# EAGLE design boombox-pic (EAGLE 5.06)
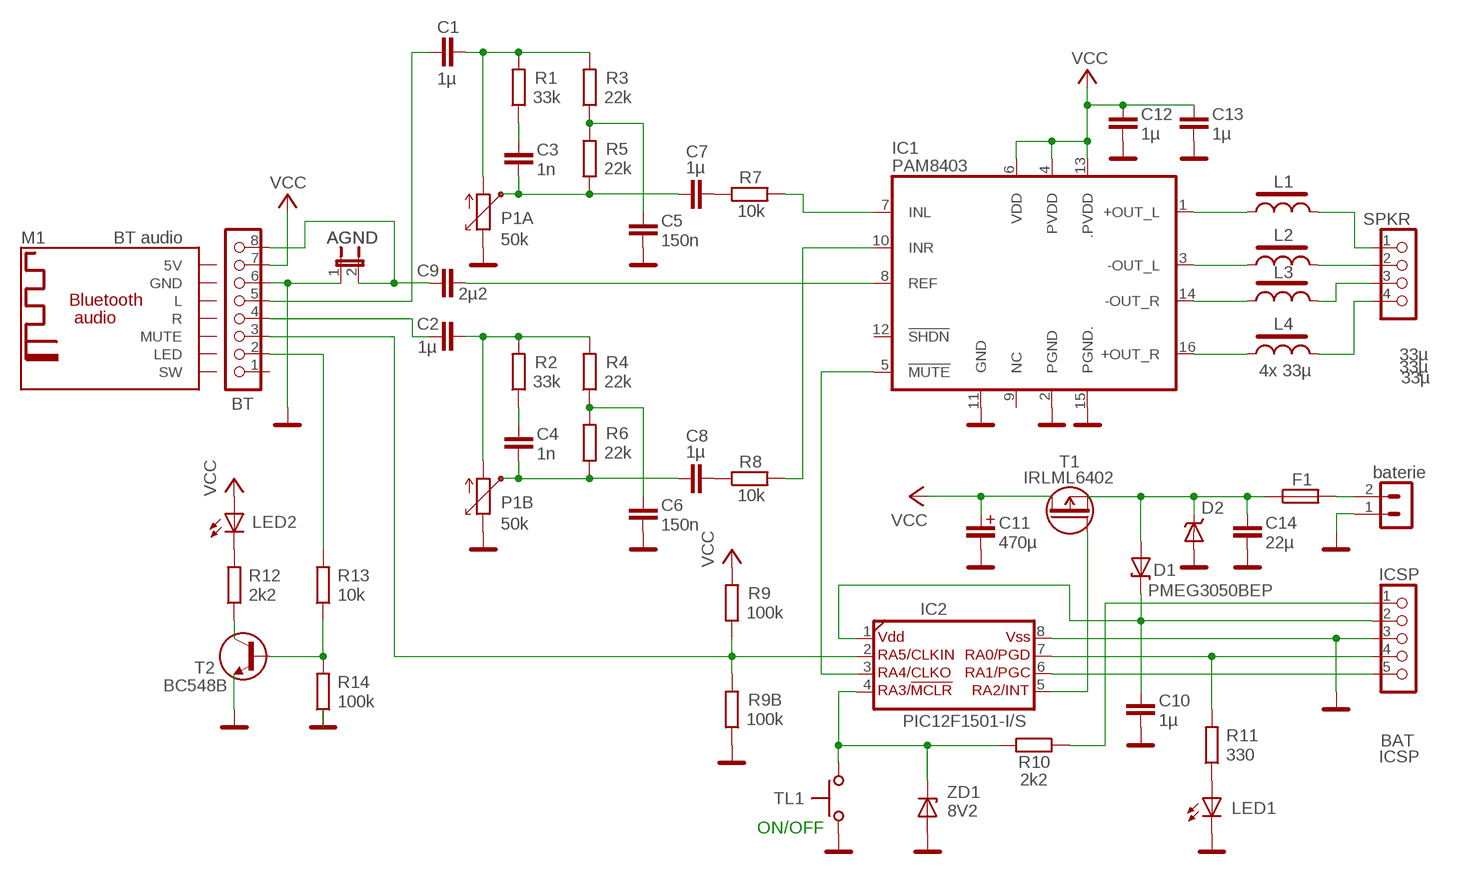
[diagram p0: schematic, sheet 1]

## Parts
AGND  JP2E_V  [1X02]
BAT  baterie  KONZ-02JST-XH  [JST-XH2]
BT  PINHD-1X8  [1X08]
C1  1µ  CSMD0805_KEMET_REFLOW  [C0805K]
C2  1µ  CSMD0805_KEMET_REFLOW  [C0805K]
C3  1n  C_KER_RM5  [C_KER_RM5]
C4  1n  C_KER_RM5  [C_KER_RM5]
C5  150n  C_5-7X3  [C5-7X3]
C6  150n  C_5-7X3  [C5-7X3]
C7  1µ  CSMD0805_KEMET_REFLOW  [C0805K]
C8  1µ  CSMD0805_KEMET_REFLOW  [C0805K]
C9  2µ2  CSMD0805_KEMET_REFLOW  [C0805K]
C10  1µ  CSMD0805_KEMET_REFLOW  [C0805K]
C11  470µ  C_ELYT_3.5-8  [CEL_3.5-8]
C12  1µ  CSMD0805_KEMET_REFLOW  [C0805K]
C13  1µ  CSMD0805_KEMET_REFLOW  [C0805K]
C14  22µ  CSMD1210  [C1210K]
D1  PMEG3050BEP  DIODA-SCHOTTKYSMA-DO214AC  [SMA-DO214AC]
D2  TRANSIL_SMA  [SMA-DO214AC]
F1  POJISTKA_MST-MSF  [POJISTKA_MST_MSF]
IC1  PAM8403  [SO16-RN]
IC2  PIC12F1501-I/S  [SO08-RN]
ICSP  ICSP  PINHD-1X5  [1X05]
L1  33µ  TLUMIVKA_SMD_SMT54  [TLUMIVKA_SMD_SMT54]
L2  33µ  TLUMIVKA_SMD_SMT54  [TLUMIVKA_SMD_SMT54]
L3  33µ  TLUMIVKA_SMD_SMT54  [TLUMIVKA_SMD_SMT54]
L4  4x 33µ  TLUMIVKA_SMD_SMT54  [TLUMIVKA_SMD_SMT54]
LED1  LEDSQR2X5  [LED2X5]
LED2  LEDSQR2X5  [LED2X5]
M1  BT audio  MODUL_BLUETOOTH  [MODUL_BLUETOOTH]
P1  50k  POT_STEREORK097  [RK097-DUAL-ELEMENT]
R1  33k  REZISTOR_SMD0805_KEMET_REFLOW  [C0805K]
R2  33k  REZISTOR_SMD0805_KEMET_REFLOW  [C0805K]
R3  22k  REZISTOR_SMD0805_KEMET_REFLOW  [C0805K]
R4  22k  REZISTOR_SMD0805_KEMET_REFLOW  [C0805K]
R5  22k  REZISTOR_SMD0805_KEMET_REFLOW  [C0805K]
R6  22k  REZISTOR_SMD0805_KEMET_REFLOW  [C0805K]
R7  10k  REZISTOR_SMD0805_KEMET_REFLOW  [C0805K]
R8  10k  REZISTOR_SMD0805_KEMET_REFLOW  [C0805K]
R9  100k  REZISTOR_SMD0805_KEMET_REFLOW  [C0805K]
R9B  100k  REZISTOR_SMD0805_KEMET_REFLOW  [C0805K]
R10  2k2  REZISTOR_SMD0805_KEMET_REFLOW  [C0805K]
R11  330  REZISTOR_SMD0805_KEMET_REFLOW  [C0805K]
R12  2k2  REZISTOR_SMD0805_KEMET_REFLOW  [C0805K]
R13  10k  REZISTOR_SMD0805_KEMET_REFLOW  [C0805K]
R14  100k  REZISTOR_SMD0805_KEMET_REFLOW  [C0805K]
SPKR  PINHD-1X4  [1X04]
T1  IRLML6402  T_PFETSOT23  [SOT23-R]
T2  BC548B  T_NPNSOT23  [SOT23-R]
TL1  TLACITKO-2P_2PIN  [2PIN_2.5MM]
ZD1  8V2  DIODA_ZENER_SOT23  [SOT23-R]

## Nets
AGND: AGND.2 BT.8 C9.1
GND: AGND.1 BAT.1 BT.6 C5.2 C6.2 C10.2 C11.- C12.2 C13.2 C14.2 D2.A IC1.2(PGND) IC1.11(GND) IC1.15(PGND.) IC2.8(VSS) ICSP.3 LED1.K(C) P1.3 P1.6 R9B.1 R14.1 T2.E TL1.P$1(P) ZD1.B(A)
N$1: BT.5 C1.1
N$2: BT.4 C2.1
N$3: C4.1 R2.1
N$4: C3.1 R1.1
N$5: C5.1 R3.1 R5.2
N$6: C6.1 R4.1 R6.2
N$7: C2.2 P1.4 R2.2 R4.2
N$8: C4.2 C8.1 P1.5 R6.1
N$9: C1.2 P1.1 R1.2 R3.2
N$10: C3.2 C7.1 P1.2 R5.1
N$11: C7.2 R7.1
N$12: C8.2 R8.1
N$13: IC1.10(INR) R8.2
N$14: IC1.7(INL) R7.2
N$15: C9.2 IC1.8(REF)
N$16: IC1.1(+OUT_L) L1.F1
N$17: IC1.3(-OUT_L) L2.F1
N$18: IC1.14(-OUT_R) L3.F1
N$19: IC1.16(+OUT_R) L4.F1
N$20: L1.F2 SPKR.1
N$21: L2.F2 SPKR.2
N$22: L3.F2 SPKR.3
N$23: L4.F2 SPKR.4
N$24: BAT.2 F1.F2
N$25: IC2.7(RA0/AN0) ICSP.4 R11.2
N$26: IC2.6(RA1/AN1) ICSP.5
N$27: C10.1 D1.K IC2.1(VCC) ICSP.2
N$28: BT.3 IC2.2(RA5/CLKIN) R9.1 R9B.2
N$29: IC1.5(!MUTE) IC2.3(RA4/AN3)
N$30: ICSP.1 R10.2
N$31: IC2.4(RA3/!MCLR) R10.1 TL1.P$2(S) ZD1.C(K)
N$32: LED1.A R11.1
N$33: C14.1 D1.A D2.K F1.F1 T1.E(S)
N$34: IC2.5(RA2/AN2) T1.B(G)
N$37: LED2.K(C) R12.2
N$38: BT.2 R13.2
N$39: R13.1 R14.2 T2.B
N$40: R12.1 T2.C
VCC: BT.7 C11.+ C12.1 C13.1 IC1.4(PVDD) IC1.6(VDD) IC1.13(.PVDD) LED2.A R9.2 T1.C(D)
Unconnected: BT.1 IC1.9(NC) IC1.12(!SHDN) M1.L M1.LED M1.MUTE M1.R M1.SW

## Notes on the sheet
- ON/OFF

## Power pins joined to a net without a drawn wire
5V: M1.5V
GND: M1.GND

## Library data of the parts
AGND = #bcs_pinhead:JP2E: JUMPER
BAT = #bcs_pinhead:KONZ-02: Konektory se zamkem - vidlice - 2pin
BT = #bcs_pinhead:PINHD-1X8: PIN HEADER
C1-C10 C12-C14 = #bcs7d:C: Kondenzatory, keramicke a foliove
C11 = #bcs7d:C_ELYT: Kondenzatory, elektrolyticke
D1 = #bcs7d:DIODA-SCHOTTKY
D2 = #bcs7d:TRANSIL: Transient voltage suppressor - TRANSIL
F1 = #bcs7d:POJISTKA_: Pojistka
IC1 = #bcs-ic1:PAM8403
IC2 = #bcs-ic1:PIC12F1501: 8-Pin FLASH-Based 8-Bit CMOS Microcontroller
ICSP = #bcs_pinhead:PINHD-1X5: PIN HEADER
L1-L4 = #bcs7d:TLUMIVKA_: Tlumivka
LED1 LED2 = #bcs7d:LED: LED
M1 = #bcs_special:MODUL_BLUETOOTH: Modul Bluetooth audio WIN-668
P1 = #bcs7d:POT_STEREO
R1-R9 R9B R10-R14 = #bcs7d:REZISTOR_
SPKR = #bcs_pinhead:PINHD-1X4: PIN HEADER
T1 = #bcs7d:T_PFET
T2 = #bcs7d:T_NPN: NPN tranzistor
TL1 = #bcs7d:TLACITKO-2P
ZD1 = #bcs7d:DIODA_ZENER

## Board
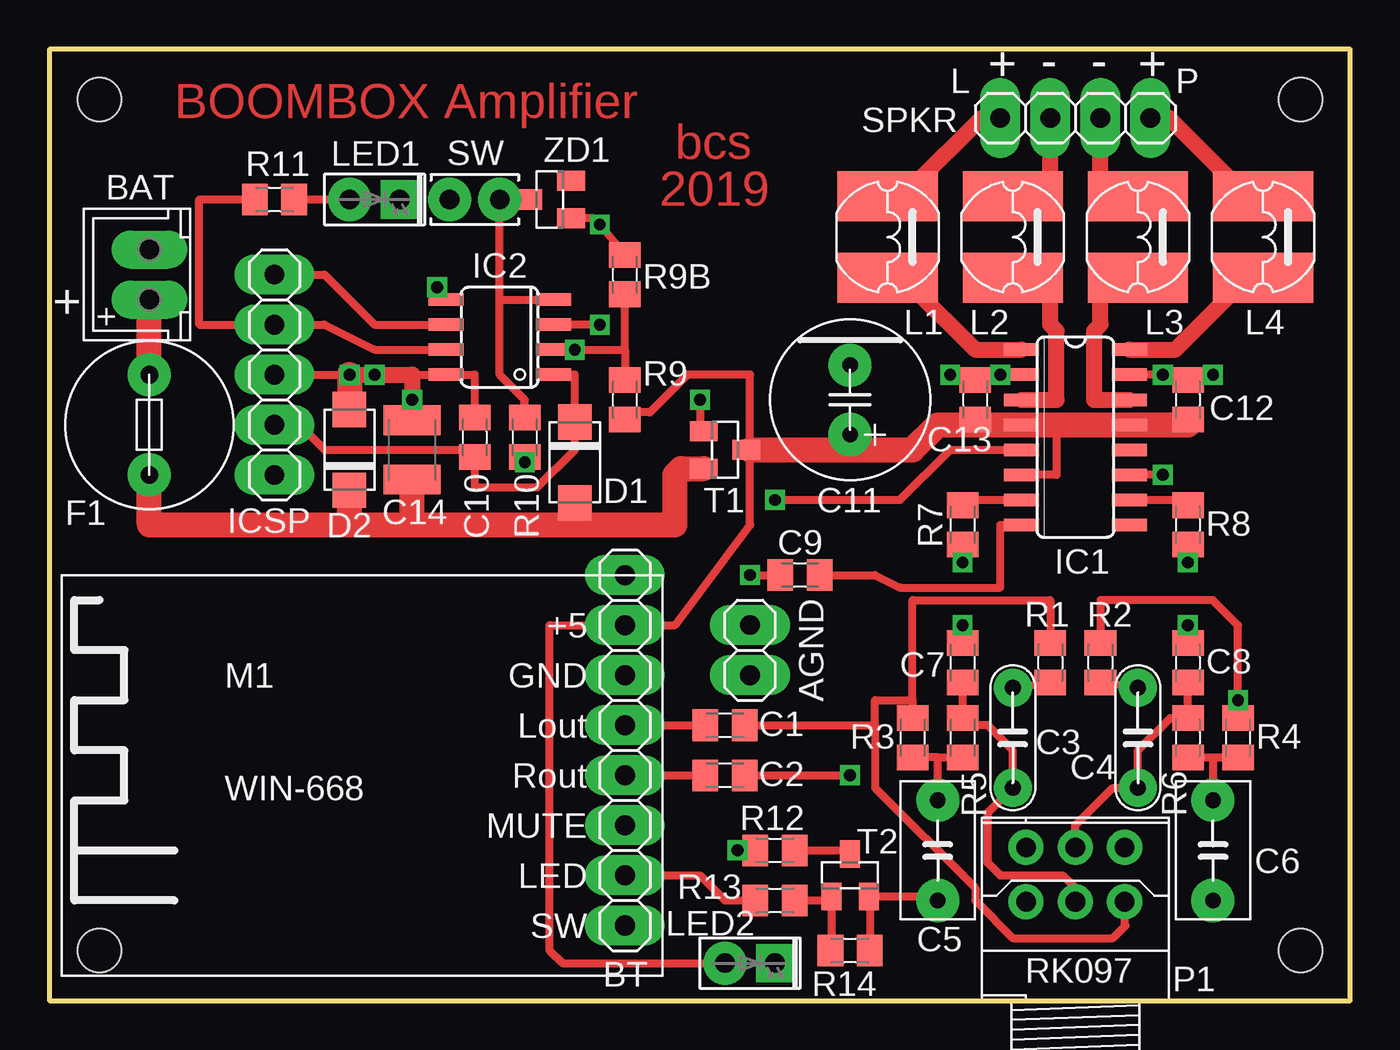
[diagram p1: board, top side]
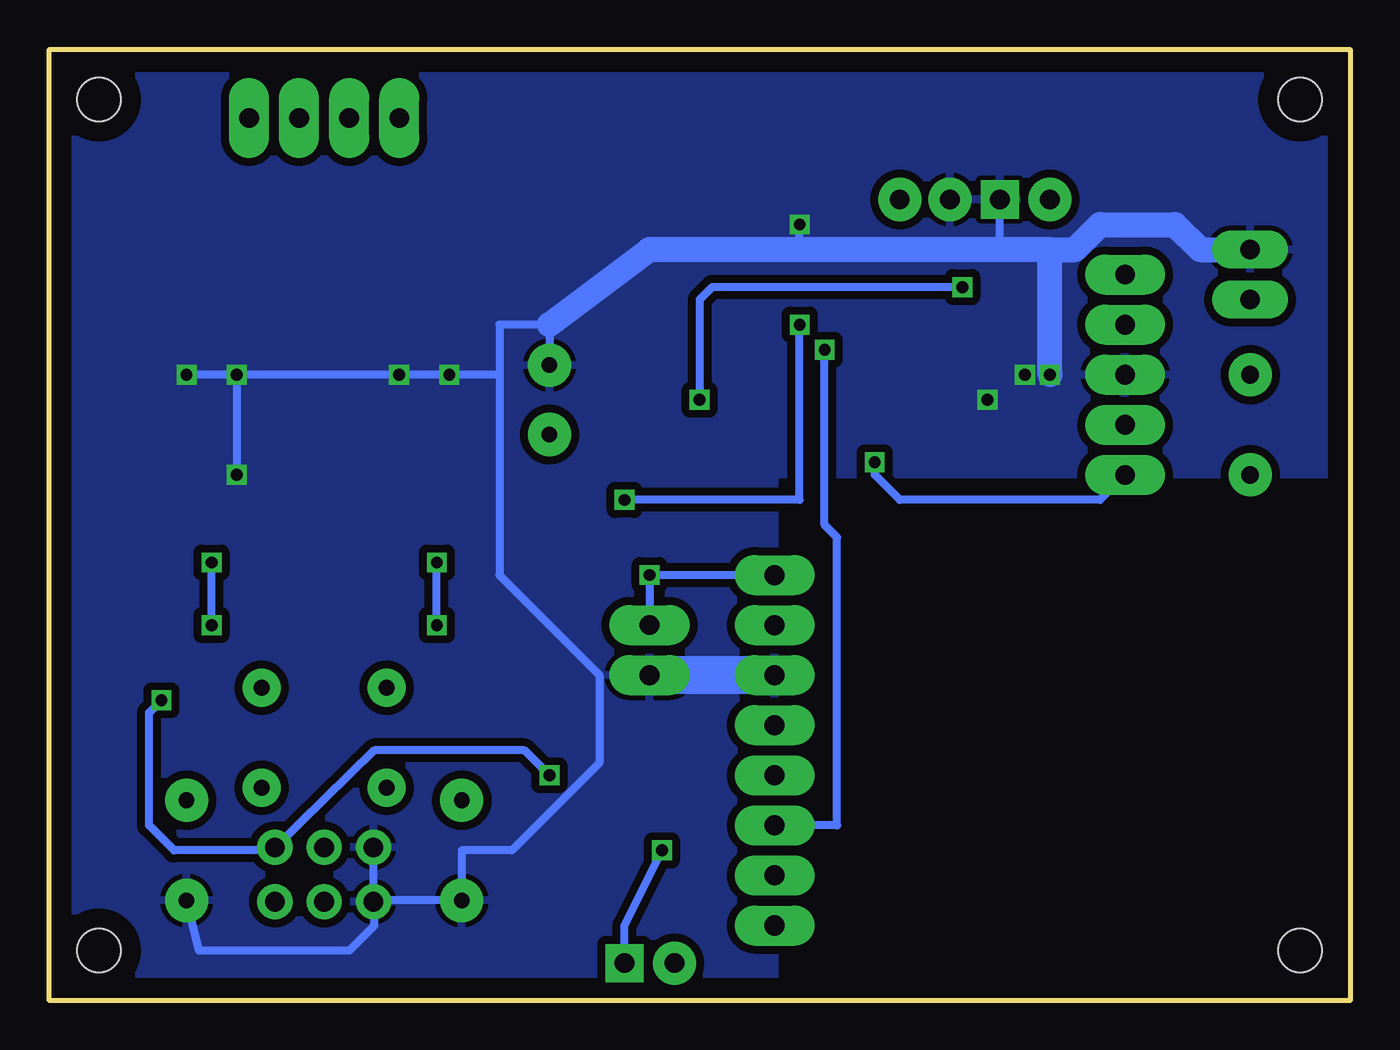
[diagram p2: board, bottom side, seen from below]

Size 66.02 x 48.26 mm. Coordinates in mm from the lower left corner, seen from the top.
Outline: 0,0 66.02,0 66.02,48.26 0,48.26 0,0
Copper layers (1*16): Top 0.035mm / dielectric 1.5mm / Bottom 0.035mm
Design rules "default": minimum track width 10mil, minimum drill 24mil, track to track 8mil, track to pad 8mil, pad to pad 8mil, via to via 8mil, smd to smd 8mil, copper to edge 40mil, drill to drill 8mil, minimum pad ring 10mil, minimum via ring 8mil, stop-mask expansion 4mil, vias tented up to drill 0mil, thermal gap 10mil
Holes 2.2 mm at 2.54,45.72 63.5,45.72 63.5,2.54 2.54,2.54

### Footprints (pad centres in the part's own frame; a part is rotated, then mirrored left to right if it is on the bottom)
1X02 = drill 1 pad 2.032 long: 1 -1.27,0; 2 1.27,0
JST-XH2 = drill 1 pad 1.93 long: 1 -1.27,0; 2 1.27,0
1X08 = drill 1.016 pad 2.032 long: 1 -8.89,0; 2 -6.35,0; 3 -3.81,0; 4 -1.27,0; 5 1.27,0; 6 3.81,0; 7 6.35,0; 8 8.89,0
C0805K = smd 1.3 x 1.6: 1 -1,0; 2 1,0
C_KER_RM5 = drill 0.8 pad 1.93 round: 1 -2.54,0; 2 2.54,0
C5-7X3 = drill 0.8 pad 2.184 round: 1 -2.54,0; 2 2.54,0
CEL_3.5-8 = drill 0.8 pad 2.184 round: + -1.762,0; - 1.762,0
C1210K = smd 1.5 x 2.9: 1 -1.5,0; 2 1.5,0
SMA-DO214AC = smd 1.8 x 1.7: A 2.05,0; K -2.05,0
POJISTKA_MST_MSF = drill 0.9 pad 2.184 round: F1 2.54,0; F2 -2.54,0
SO16-RN = smd 0.635 x 1.778: 1 -4.445,-2.731; 2 -3.175,-2.731; 3 -1.905,-2.731; 4 -0.635,-2.731; 5 0.635,-2.731; 6 1.905,-2.731; 7 3.175,-2.731; 8 4.445,-2.731; 9 4.445,2.731; 10 3.175,2.731; 11 1.905,2.731; 12 0.635,2.731; 13 -0.635,2.731; 14 -1.905,2.731; 15 -3.175,2.731; 16 -4.445,2.731
SO08-RN = smd 0.635 x 1.778: 1 -1.905,-2.731; 2 -0.635,-2.731; 3 0.635,-2.731; 4 1.905,-2.731; 5 1.905,2.731; 6 0.635,2.731; 7 -0.635,2.731; 8 -1.905,2.731
1X05 = drill 1 pad 2.032 long: 1 -5.08,0; 2 -2.54,0; 3 0,0; 4 2.54,0; 5 5.08,0
TLUMIVKA_SMD_SMT54 = smd 2.54 x 5.08: F1 2.064,0; F2 -2.064,0
LED2X5 = drill 1 pad 2.184 round: A -1.27,0 | drill 1 pad 1.93 square: K 1.27,0
MODUL_BLUETOOTH = drill 1 pad 1.93 square: 5V 0,7.62; GND 0,5.08; L 0,2.54; LED 0,-5.08; MUTE 0,-2.54; R 0,0; SW 0,-7.62
RK097-DUAL-ELEMENT = drill 1 pad 1.778 round: 1 2.5,-0.06; 2 0,-0.06; 3 -2.5,-0.06; 4 2.5,2.69; 5 0,2.69; 6 -2.5,2.69
1X04 = drill 1 pad 2.032 long: 1 -3.81,0; 2 -1.27,0; 3 1.27,0; 4 3.81,0
SOT23-R = smd 1.016 x 1.397: B -0.953,-1.079; C 0,1.079; E 0.953,-1.079
2PIN_2.5MM = drill 1 pad 2.184 round: P$1 -1.27,0; P$2 1.27,0

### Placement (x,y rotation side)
AGND  35.56,17.78 90 top
BAT  5.08,36.83 270 top
BT  29.21,12.7 90 top
C1  34.29,13.97 0 top
C2  34.29,11.43 0 top
C3  48.9,13.34 270 top
C4  55.24,13.34 270 top
C5  45.09,7.62 270 top
C6  59.05,7.62 270 top
C7  46.35,17.14 90 top
C8  57.78,17.14 90 top
C9  38.1,21.59 0 top
C10  21.59,28.57 90 top
C11  40.64,30.48 90 top
C12  57.78,30.48 90 top
C13  46.99,30.48 90 top
C14  18.41,27.94 90 top
D1  26.67,27.3 270 top
D2  15.24,27.94 90 top
F1  5.08,29.21 270 top
IC1  52.07,28.57 270 top
IC2  22.86,33.66 90 top
ICSP  11.43,31.75 90 top
L1  42.55,38.73 270 top
L2  48.9,38.73 270 top
L3  55.24,38.73 270 top
L4  61.59,38.73 270 top
LED1  16.51,40.64 0 top
LED2  35.56,1.91 0 top
M1  29.21,11.43 0 top
P1  52.07,5.08 0 top
R1  50.8,17.14 90 top
R2  53.34,17.14 90 top
R3  43.81,13.34 90 top
R4  60.33,13.34 90 top
R5  46.35,13.34 270 top
R6  57.78,13.34 270 top
R7  46.35,24.13 90 top
R8  57.78,24.13 90 top
R9  29.21,30.48 270 top
R9B  29.21,36.83 270 top
R10  24.13,28.57 270 top
R11  11.43,40.64 180 top
R12  36.83,7.62 180 top
R13  36.83,5.08 180 top
R14  40.64,2.54 180 top
SPKR  52.07,44.77 0 top
T1  34.29,27.94 270 top
T2  40.64,6.35 0 top
TL1  21.59,40.64 0 top
ZD1  25.4,40.64 90 top

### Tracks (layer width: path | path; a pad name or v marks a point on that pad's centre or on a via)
AGND  (via drill 0.6)
  Top 0.406: v35.56,21.59 C9.1
  Bottom 0.406: BT.8 v35.56,21.59 AGND.2
GND  (via drill 0.6)
  Top 0.406: v56.52,26.67 IC1.11 | 18.41,31.75 IC2.8 21.59,31.75 C10.2 | ZD1.B 27.62,39.69 v27.94,39.37 R9B.1 | 41.91,5.27 T2.E | 41.91,5.27 44.9,5.27 C5.2 | R14.1 41.64,5 41.91,5.27 | v56.52,31.75 57.15,31.75 | 57.15,31.75 57.78,31.75 C12.2 58.05,31.75 | 46.99,31.75 v48.26,31.75 IC1.2 | 46.99,31.75 C13.2 | v45.72,31.75 46.99,31.75 | 57.15,31.75 IC1.15 | ICSP.3 v15.24,31.75
  Top 0.813: v15.24,31.75 v16.51,31.75 18.41,31.75 v18.41,30.48 C14.2
  Top 1.27: v15.24,31.75 D2.A
  Bottom 0.406: 49.51,5.08 C5.2 45.09,7.62 42.55,7.62 38.1,12.06 38.1,16.51 43.18,21.59 43.18,31.75 | 49.51,5.08 P1.3 49.53,4.98 49.53,3.81 50.8,2.54 58.42,2.54 C6.2 | v56.52,31.75 v56.52,26.67 | 17.78,38.1 LED1.K | 27.94,38.1 v27.94,39.37 | 49.51,5.08 49.57,5.08 P1.6 | 43.18,31.75 v45.72,31.75 v48.26,31.75 v56.52,31.75 | 40.64,31.75 C11.- 40.64,34.29 43.18,34.29 43.18,31.75 | v56.52,31.75 v59.05,31.75
  Bottom 1.27: 15.24,38.1 17.78,38.1 27.94,38.1 35.56,38.1 40.64,34.29 | v15.24,31.75 15.24,38.1 | BAT.1 7.62,38.1 8.89,39.37 12.7,39.37 13.97,38.1 15.24,38.1
  Bottom 1.93: BT.6 AGND.1
  pour Bottom (isolate 0.406): 67.31,0 67.31,48.26 0,48.26 0,26.67 29.21,26.67 29.21,0
N$1
  Top 0.406: BT.5 C1.1
N$2
  Top 0.406: BT.4 C2.1
N$3
  Top 0.406: C4.1 R2.1
N$4
  Top 0.406: C3.1 R1.1
N$5
  Top 0.406: 45.09,12.34 R3.1 | 45.09,12.34 R5.2 | C5.1 45.09,12.34
N$6
  Top 0.406: R6.2 59.05,12.34 | 59.05,12.34 R4.1 | 59.05,12.34 C6.1
N$7  (via drill 0.6)
  Top 0.406: R2.2 53.34,20.32 59.05,20.32 60.33,19.05 v60.33,15.24 R4.2 | C2.2 v40.64,11.43
  Bottom 0.406: v60.33,15.24 60.96,14.61 60.96,8.89 59.69,7.62 54.72,7.62 54.61,7.73 | v40.64,11.43 41.91,12.7 49.53,12.7 54.61,7.73 | 54.61,7.73 P1.4
N$8
  Top 0.406: P1.5 52.07,8.89 53.98,10.79 C4.2 55.24,12.7 56.88,14.34 R6.1 C8.1
N$9
  Top 0.406: 43.81,15.24 43.81,20.32 50.8,20.32 R1.2 | 43.81,15.24 R3.2 | P1.1 54.57,3.85 54.61,3.81 53.98,3.17 48.9,3.17 46.99,5.08 46.99,5.71 41.91,10.79 41.91,13.97 | 41.91,13.97 41.91,15.24 43.81,15.24 | C1.2 41.91,13.97
N$10
  Top 0.406: P1.2 52.07,5.71 51.44,6.35 48.26,6.35 47.62,6.99 47.62,9.53 C3.2 48.9,12.7 47.62,13.97 46.35,13.97 R5.1 C7.1
N$11  (via drill 0.6)
  Top 0.406: C7.2 v46.35,19.05 | v46.35,22.23 R7.1
  Bottom 0.406: v46.35,19.05 v46.35,22.23
N$12  (via drill 0.6)
  Top 0.406: C8.2 v57.78,19.05 | v57.78,22.23 R8.1
  Bottom 0.406: v57.78,19.05 v57.78,22.23
N$13
  Top 0.406: IC1.10 57.52,25.4 R8.2
N$14
  Top 0.406: IC1.7 46.62,25.4 R7.2
N$15
  Top 0.406: C9.2 41.91,21.59 43.18,20.95 48.26,20.95 48.26,24.13 IC1.8
N$16
  Top 0.813: IC1.1 46.99,33.02 43.81,36.2 42.55,36.2 L1.F1
N$17
  Top 0.813: IC1.3 51.12,30.48 51.12,33.97 50.8,34.29 50.8,36.51 48.9,36.51 L2.F1
N$18
  Top 0.813: IC1.14 53.02,30.48 53.02,33.97 53.34,34.29 53.34,36.67 L3.F1
N$19
  Top 0.813: IC1.16 57.15,33.02 60.33,36.2 61.59,36.2 L4.F1
N$20
  Top 0.813: L1.F2 43.81,41.27 47.31,44.77 SPKR.1
N$21
  Top 0.406: L2.F2 50.8,41.91
  Top 0.813: 50.8,41.91 SPKR.2
N$22
  Top 0.406: L3.F2 53.34,41.91
  Top 0.813: 53.34,41.91 SPKR.3
N$23
  Top 0.813: SPKR.4 56.83,44.77 60.01,41.59 L4.F2
N$24
  Top 1.27: F1.F2 BAT.2
N$25
  Top 0.406: IC2.7 16.51,33.02 13.97,34.29 ICSP.4 7.62,34.29 7.62,40.64 R11.2
N$26
  Top 0.406: ICSP.5 13.97,36.83 16.51,34.29 IC2.6
N$27
  Top 0.406: ICSP.2 12.7,29.21 13.97,27.94 21.59,27.94 | D1.K 26.67,31.75 IC2.1 | D1.K 26.67,29.21 | 21.59,27.94 C10.1 | 21.59,27.94 21.59,26.04 24.77,26.04 26.67,27.94 D1.K
N$28  (via drill 0.6)
  Top 0.406: IC2.2 v26.67,33.02 29.21,33.02 | 29.21,33.02 R9.1 | 29.21,33.02 R9B.2
  Bottom 0.406: v26.67,33.02 26.67,24.13 26.04,23.5 26.04,8.89 BT.3
N$29  (via drill 0.6)
  Top 0.406: v27.94,34.29 IC2.3 | v36.83,25.4 43.18,25.4 45.72,27.94 IC1.5
  Bottom 0.406: v27.94,34.29 27.94,25.4 v36.83,25.4
N$30  (via drill 0.6)
  Top 0.406: v24.13,27.3 R10.2
  Bottom 0.406: ICSP.1 12.7,25.4 22.86,25.4 24.13,26.67 v24.13,27.3
N$31
  Top 0.406: ZD1.C TL1.P$2 22.86,35.56 | 22.86,35.56 IC2.4 | R10.1 24.13,30.48 22.86,31.75 22.86,35.56
N$32
  Top 0.406: R11.1 LED1.A
N$33
  Top 0.406: 26.67,24.13 D1.A
  Top 1.27: 15.24,24.13 5.08,24.13 F1.F1 | 15.24,24.13 18.41,24.13 | 18.41,24.13 26.67,24.13 31.75,24.13 31.75,26.67 32.07,26.99 T1.E | 15.24,24.13 D2.K | 18.41,24.13 C14.1
N$34  (via drill 0.6)
  Top 0.406: T1.B 33.21,29.02 33.02,29.21 v33.02,30.48 | IC2.5 v19.68,36.2
  Bottom 0.406: v33.02,30.48 33.02,35.56 32.38,36.2 v19.68,36.2
N$37  (via drill 0.6)
  Top 0.406: v34.92,7.62 R12.2
  Bottom 0.406: v34.92,7.62 36.83,3.81 LED2.K
N$38
  Top 0.406: BT.2 33.02,6.35 34.29,5.08 R13.2
N$39
  Top 0.406: R14.2 39.69,2.59 T2.B 39.5,5.08 R13.1
N$40
  Top 0.406: T2.C 40.64,7.62 R12.1
VCC
  Top 0.406: IC1.6 51.12,26.67 51.12,29.21 | 57.78,29.21 C12.1 | 40.64,27.94 C11.+ | LED2.A 26.04,1.91 25.4,2.54 25.4,19.05 BT.7 31.75,19.05 35.56,24.13 35.56,27.94 T1.C 35.56,28.13 35.56,31.75 32.38,31.75 30.48,29.84 29.84,29.84 29.21,29.21 R9.2 | 46.99,29.21 C13.1
  Top 1.27: 57.78,29.21 IC1.13 51.12,29.21 IC1.4 46.99,29.21 45.09,29.21 43.81,27.94 40.64,27.94 35.56,27.94

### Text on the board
Top: BOOMBOX Amplifier | bcs | 2019
tPlace: + | - | - | + | L | P | SW | +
